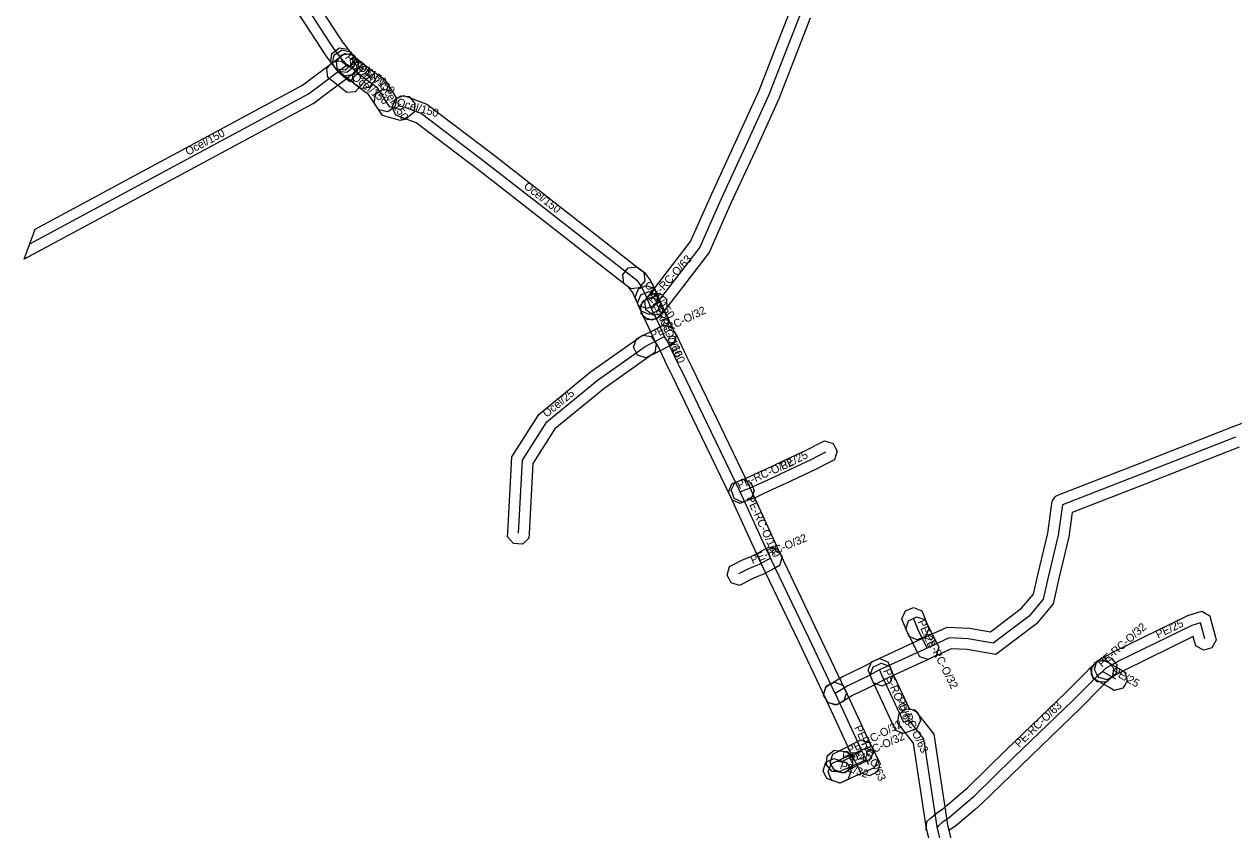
# Model space of a CAD drawing. Extents: x -783553 to -783321, y -1065190 to -1064961.
# Drawn here: x -783552.6 to -783439.3, y -1065147.9 to -1065072.4 of the extents above; entities that cross this region are included whole.
import ezdxf

# ---------------------------------------------------------------- set-up
doc = ezdxf.new("R2010")
doc.units = 0
for name, color, linetype in [('1', 7, 'Continuous'), ('28', 7, 'Continuous'), ('30', 7, 'Continuous'), ('Plyn', 7, 'Continuous')]:
    doc.layers.add(name, color=color, linetype=linetype)

msp = doc.modelspace()

# ---------------------------------------------------------------- linework, layer by layer
at = {"layer": '1'}
for points in [[(-783527.9, -1065066.2), (-783522.74, -1065074.15), (-783522.73, -1065074.15), (-783522.07, -1065075.01), (-783521.81, -1065075.34), (-783521.92, -1065076.16), (-783522.24, -1065076.42), (-783522.57, -1065076.67), (-783523.39, -1065076.57), (-783523.65, -1065076.24), (-783524.38, -1065075.3), (-783524.42, -1065075.24), (-783529.69, -1065067.11)], [(-783479, -1065071.78), (-783480.4, -1065075.41), (-783481.93, -1065079.36), (-783484.16, -1065084.26), (-783486.42, -1065089.15), (-783488.45, -1065093.77), (-783492.65, -1065099.2), (-783492.9, -1065099.53), (-783493.72, -1065099.64), (-783494.05, -1065099.38), (-783494.38, -1065099.13), (-783494.48, -1065098.31), (-783494.23, -1065097.98), (-783490.19, -1065092.74), (-783488.24, -1065088.33), (-783485.98, -1065083.42), (-783483.77, -1065078.58), (-783482.26, -1065074.69), (-783480.88, -1065071.1)], [(-783438.79, -1065112.01), (-783447.61, -1065115.48), (-783454.44, -1065118.14), (-783454.76, -1065120.43), (-783455.71, -1065124.44), (-783456.23, -1065126.71), (-783457.79, -1065128.58), (-783461.59, -1065131.45), (-783464.29, -1065130.98), (-783465.77, -1065130.91), (-783467.6, -1065131.75), (-783472.04, -1065133.8), (-783473, -1065134.31), (-783475.03, -1065135.3), (-783476.15, -1065135.97), (-783476.5, -1065136.18), (-783477.3, -1065135.98), (-783477.52, -1065135.62), (-783477.73, -1065135.27), (-783477.53, -1065134.47), (-783477.17, -1065134.25), (-783475.99, -1065133.54), (-783473.92, -1065132.53), (-783472.94, -1065132), (-783468.44, -1065129.93), (-783466.17, -1065128.89), (-783464.07, -1065128.98), (-783462.1, -1065129.33), (-783459.18, -1065127.12), (-783458.07, -1065125.79), (-783457.65, -1065123.98), (-783456.72, -1065120.07), (-783456.34, -1065117.28), (-783456.3, -1065117.01), (-783455.97, -1065116.59), (-783455.71, -1065116.49), (-783448.33, -1065113.62), (-783439.51, -1065110.15), (-783431.95, -1065107.28)], [(-783468.13, -1065147.92), (-783468.06, -1065147.1), (-783467.74, -1065146.83), (-783467.63, -1065146.74), (-783467.15, -1065146.33), (-783466.56, -1065145.92), (-783465.68, -1065145.17), (-783464.84, -1065144.45), (-783464.26, -1065143.95), (-783460.63, -1065140.4), (-783455.07, -1065135.05), (-783453.09, -1065133.06), (-783452.81, -1065132.76), (-783452.56, -1065132.53), (-783452.26, -1065132.27), (-783451.95, -1065132), (-783451.12, -1065132.06), (-783450.85, -1065132.38), (-783450.58, -1065132.69), (-783450.65, -1065133.52), (-783450.96, -1065133.79), (-783451.22, -1065134.01), (-783451.4, -1065134.18), (-783451.67, -1065134.46), (-783453.67, -1065136.47), (-783459.23, -1065141.84), (-783462.91, -1065145.43), (-783463.54, -1065145.97), (-783464.38, -1065146.69), (-783465.34, -1065147.5), (-783465.93, -1065147.91)], [(-783467.67, -1065149.47), (-783468.08, -1065147.79), (-783469.3, -1065139.75), (-783470.52, -1065138.21), (-783470.77, -1065137.88), (-783470.67, -1065137.06), (-783470.35, -1065136.8), (-783470.02, -1065136.55), (-783469.2, -1065136.65), (-783468.95, -1065136.97), (-783467.4, -1065138.93), (-783466.12, -1065147.41), (-783465.71, -1065149.09)]]:
    msp.add_lwpolyline(points, dxfattribs=at)
for points in [[(-783523.22, -1065076.78), (-783523.48, -1065076.46), (-783523.65, -1065076.24), (-783523.9, -1065075.92), (-783523.8, -1065075.09), (-783523.47, -1065074.84), (-783523.14, -1065074.58), (-783522.32, -1065074.69), (-783522.07, -1065075.01), (-783521.9, -1065075.23), (-783521.65, -1065075.55), (-783521.75, -1065076.37), (-783522.08, -1065076.63), (-783522.4, -1065076.88)], [(-783522.07, -1065074.95), (-783521.86, -1065075.28), (-783521.76, -1065075.35), (-783521.43, -1065075.59), (-783521.29, -1065076.41), (-783521.53, -1065076.74), (-783521.77, -1065077.08), (-783522.58, -1065077.22), (-783522.92, -1065076.98), (-783523.34, -1065076.68), (-783523.53, -1065076.38), (-783523.76, -1065076.03), (-783523.58, -1065075.22), (-783523.23, -1065075), (-783522.88, -1065074.77)], [(-783525.58, -1065079.82), (-783552.64, -1065094.4), (-783551.62, -1065091.57), (-783526.55, -1065078.07), (-783525.27, -1065077.11), (-783523.83, -1065076.03), (-783522.94, -1065075.36), (-783522.61, -1065075.11), (-783521.79, -1065075.23), (-783521.54, -1065075.56), (-783521.3, -1065075.89), (-783521.41, -1065076.71), (-783521.74, -1065076.96), (-783522.63, -1065077.63), (-783524.07, -1065078.71), (-783525.48, -1065079.77), (-783525.55, -1065079.81), (-783525.57, -1065079.81)], [(-783522.61, -1065076.05), (-783522.22, -1065076.36), (-783522.1, -1065076.24), (-783521.82, -1065075.94), (-783520.99, -1065075.91), (-783520.69, -1065076.2), (-783520.39, -1065076.48), (-783520.36, -1065077.31), (-783520.65, -1065077.61), (-783521.01, -1065077.99), (-783521.35, -1065078.39), (-783521.62, -1065078.69), (-783522.42, -1065078.76), (-783522.73, -1065078.51), (-783523.86, -1065077.61), (-783524.18, -1065077.36), (-783524.27, -1065076.53), (-783524.02, -1065076.21), (-783523.76, -1065075.89), (-783522.94, -1065075.79)], [(-783521.13, -1065078.4), (-783521.45, -1065078.14), (-783521.78, -1065077.88), (-783522, -1065077.71), (-783522.96, -1065076.95), (-783523.29, -1065076.69), (-783523.38, -1065075.87), (-783523.13, -1065075.54), (-783522.87, -1065075.22), (-783522.05, -1065075.12), (-783521.72, -1065075.38), (-783520.76, -1065076.14), (-783520.54, -1065076.31), (-783520.21, -1065076.57), (-783519.89, -1065076.82), (-783519.79, -1065077.65), (-783520.05, -1065077.97), (-783520.31, -1065078.3)], [(-783520.57, -1065076.3), (-783520.24, -1065076.55), (-783518.89, -1065077.54), (-783518.45, -1065078.21), (-783518.37, -1065078.34), (-783518.36, -1065078.35), (-783517.96, -1065078.96), (-783517.74, -1065079.31), (-783517.91, -1065080.12), (-783518.25, -1065080.35), (-783518.6, -1065080.57), (-783519.41, -1065080.4), (-783519.64, -1065080.06), (-783520.03, -1065079.45), (-783520.04, -1065079.44), (-783520.13, -1065079.31), (-783520.37, -1065078.94), (-783521.43, -1065078.16), (-783521.76, -1065077.91), (-783521.89, -1065077.09), (-783521.64, -1065076.76), (-783521.39, -1065076.43)], [(-783517.64, -1065079.25), (-783517.61, -1065079.26), (-783517.39, -1065079.08), (-783516.57, -1065079.15), (-783516.3, -1065079.47), (-783516.04, -1065079.79), (-783516.11, -1065080.61), (-783516.43, -1065080.88), (-783516.56, -1065080.99), (-783516.73, -1065081.13), (-783516.92, -1065081.29), (-783517.4, -1065081.39), (-783517.64, -1065081.32), (-783518.18, -1065081.17), (-783519.07, -1065080.92), (-783519.64, -1065080.06), (-783519.86, -1065079.71), (-783519.69, -1065078.9), (-783519.35, -1065078.67), (-783519, -1065078.45), (-783518.19, -1065078.62), (-783517.96, -1065078.96), (-783517.81, -1065079.2)], [(-783517.11, -1065079.03), (-783516.72, -1065079.17), (-783514.92, -1065079.84), (-783508.76, -1065084.52), (-783502.88, -1065089.1), (-783498.15, -1065092.81), (-783494.91, -1065095.34), (-783494.58, -1065095.59), (-783494.48, -1065096.42), (-783494.73, -1065096.74), (-783494.98, -1065097.07), (-783495.81, -1065097.17), (-783496.13, -1065096.92), (-783499.39, -1065094.39), (-783504.12, -1065090.68), (-783509.98, -1065086.1), (-783515.9, -1065081.61), (-783517.42, -1065081.05), (-783517.81, -1065080.9), (-783518.15, -1065080.15), (-783518.01, -1065079.76), (-783517.86, -1065079.37)], [(-783495.23, -1065095.09), (-783494.9, -1065095.34), (-783494.51, -1065095.65), (-783493.93, -1065096.45), (-783493.42, -1065097.5), (-783493.24, -1065097.88), (-783493.51, -1065098.66), (-783493.88, -1065098.84), (-783494.26, -1065099.02), (-783495.04, -1065098.75), (-783495.22, -1065098.38), (-783495.65, -1065097.49), (-783495.97, -1065097.05), (-783496.14, -1065096.92), (-783496.46, -1065096.66), (-783496.56, -1065095.84), (-783496.31, -1065095.51), (-783496.05, -1065095.19)], [(-783494.84, -1065099.27), (-783495, -1065098.89), (-783495.24, -1065098.33), (-783495.4, -1065097.95), (-783495.09, -1065097.18), (-783494.71, -1065097.02), (-783494.33, -1065096.86), (-783493.56, -1065097.17), (-783493.4, -1065097.55), (-783493.16, -1065098.11), (-783493, -1065098.49), (-783493.31, -1065099.26), (-783493.69, -1065099.42), (-783494.07, -1065099.58)], [(-783494.61, -1065099.81), (-783494.77, -1065099.43), (-783495, -1065098.89), (-783495.16, -1065098.51), (-783494.85, -1065097.74), (-783494.47, -1065097.58), (-783494.09, -1065097.42), (-783493.32, -1065097.73), (-783493.16, -1065098.11), (-783492.93, -1065098.65), (-783492.77, -1065099.03), (-783493.08, -1065099.8), (-783493.46, -1065099.96), (-783493.84, -1065100.12)], [(-783477.39, -1065135.91), (-783477.56, -1065135.54), (-783480.03, -1065130.33), (-783483.6, -1065122.85), (-783486.46, -1065116.64), (-783489.57, -1065110.16), (-783491.9, -1065105.36), (-783492.09, -1065104.98), (-783492.39, -1065104.39), (-783492.62, -1065103.89), (-783493.08, -1065102.89), (-783493.18, -1065102.67), (-783493.52, -1065102.1), (-783493.77, -1065101.56), (-783494.09, -1065100.88), (-783494.61, -1065099.75), (-783494.74, -1065099.49), (-783494.93, -1065099.12), (-783494.67, -1065098.33), (-783494.3, -1065098.15), (-783493.93, -1065097.96), (-783493.14, -1065098.22), (-783492.96, -1065098.59), (-783492.81, -1065098.89), (-783492.27, -1065100.04), (-783491.96, -1065100.72), (-783491.74, -1065101.16), (-783491.4, -1065101.75), (-783491.26, -1065102.05), (-783490.8, -1065103.05), (-783490.59, -1065103.52), (-783490.31, -1065104.06), (-783490.1, -1065104.46), (-783487.77, -1065109.3), (-783484.66, -1065115.78), (-783481.8, -1065122.01), (-783478.23, -1065129.47), (-783475.76, -1065134.68), (-783475.58, -1065135.06), (-783475.86, -1065135.84), (-783476.23, -1065136.01), (-783476.61, -1065136.19)], [(-783494.87, -1065098.67), (-783494.59, -1065098.37), (-783494.18, -1065097.92), (-783493.9, -1065097.61), (-783493.07, -1065097.57), (-783492.77, -1065097.85), (-783492.46, -1065098.13), (-783492.42, -1065098.96), (-783492.7, -1065099.26), (-783493.11, -1065099.71), (-783493.39, -1065100.02), (-783494.22, -1065100.06), (-783494.52, -1065099.78), (-783494.83, -1065099.5)], [(-783495.28, -1065101.85), (-783494.91, -1065101.67), (-783494.42, -1065101.42), (-783493.96, -1065101.2), (-783493.31, -1065100.85), (-783493.08, -1065100.74), (-783492.71, -1065100.55), (-783491.92, -1065100.81), (-783491.74, -1065101.18), (-783491.55, -1065101.55), (-783491.81, -1065102.34), (-783492.18, -1065102.52), (-783492.39, -1065102.63), (-783493.06, -1065102.98), (-783493.54, -1065103.22), (-783494.01, -1065103.45), (-783494.38, -1065103.64), (-783495.17, -1065103.38), (-783495.35, -1065103.01), (-783495.54, -1065102.64)], [(-783507.34, -1065120.43), (-783507.32, -1065120.02), (-783506.95, -1065112.91), (-783504.43, -1065108.96), (-783499.56, -1065104.95), (-783495.04, -1065101.75), (-783494.7, -1065101.51), (-783493.88, -1065101.64), (-783493.65, -1065101.98), (-783493.41, -1065102.32), (-783493.54, -1065103.14), (-783493.88, -1065103.38), (-783498.34, -1065106.54), (-783502.92, -1065110.3), (-783504.98, -1065113.54), (-783505.33, -1065120.12), (-783505.35, -1065120.54), (-783505.96, -1065121.09), (-783506.38, -1065121.07), (-783506.79, -1065121.05)], [(-783476.72, -1065113.19), (-783477.09, -1065113.38), (-783478.48, -1065114.1), (-783481.35, -1065115.45), (-783481.48, -1065115.51), (-783483.27, -1065116.32), (-783483.34, -1065116.36), (-783484.22, -1065116.78), (-783484.98, -1065117.04), (-783485.37, -1065117.18), (-783486.11, -1065116.82), (-783486.25, -1065116.43), (-783486.39, -1065116.04), (-783486.03, -1065115.29), (-783485.64, -1065115.16), (-783484.98, -1065114.92), (-783484.31, -1065114.61), (-783484.22, -1065114.55), (-783482.34, -1065113.7), (-783482.23, -1065113.65), (-783479.36, -1065112.3), (-783478.01, -1065111.6), (-783477.64, -1065111.41), (-783476.85, -1065111.66), (-783476.66, -1065112.03), (-783476.47, -1065112.4)], [(-783486.34, -1065115.46), (-783485.96, -1065115.29), (-783485.71, -1065115.19), (-783485.33, -1065115.02), (-783484.56, -1065115.32), (-783484.4, -1065115.7), (-783484.23, -1065116.08), (-783484.53, -1065116.85), (-783484.91, -1065117.02), (-783485.16, -1065117.12), (-783485.54, -1065117.29), (-783486.31, -1065116.99), (-783486.47, -1065116.61), (-783486.64, -1065116.23)], [(-783481.86, -1065123.11), (-783482.23, -1065123.31), (-783483.35, -1065123.91), (-783483.84, -1065124.12), (-783484.48, -1065124.39), (-783485.23, -1065124.78), (-783485.6, -1065124.98), (-783486.39, -1065124.74), (-783486.58, -1065124.37), (-783486.78, -1065124), (-783486.54, -1065123.21), (-783486.17, -1065123.02), (-783485.34, -1065122.57), (-783484.61, -1065122.28), (-783484.21, -1065122.11), (-783483.17, -1065121.55), (-783482.81, -1065121.35), (-783482.02, -1065121.59), (-783481.82, -1065121.96), (-783481.62, -1065122.32)], [(-783468.54, -1065127.36), (-783468.38, -1065127.74), (-783468.02, -1065128.62), (-783467.87, -1065129.01), (-783468.19, -1065129.77), (-783468.57, -1065129.93), (-783468.96, -1065130.08), (-783469.72, -1065129.76), (-783469.88, -1065129.38), (-783470.24, -1065128.5), (-783470.39, -1065128.11), (-783470.07, -1065127.35), (-783469.69, -1065127.19), (-783469.3, -1065127.03)], [(-783468.72, -1065131.66), (-783468.91, -1065131.29), (-783469.84, -1065129.45), (-783470.03, -1065129.08), (-783469.77, -1065128.29), (-783469.4, -1065128.11), (-783469.03, -1065127.92), (-783468.24, -1065128.18), (-783468.06, -1065128.55), (-783467.13, -1065130.39), (-783466.94, -1065130.76), (-783467.2, -1065131.54), (-783467.57, -1065131.73), (-783467.94, -1065131.92)], [(-783442.97, -1065130.23), (-783443.1, -1065129.77), (-783449.64, -1065132.97), (-783450.79, -1065133.61), (-783451.15, -1065133.81), (-783451.95, -1065133.59), (-783452.15, -1065133.23), (-783452.35, -1065132.87), (-783452.13, -1065132.07), (-783451.77, -1065131.87), (-783450.56, -1065131.19), (-783443.61, -1065127.8), (-783442.7, -1065127.52), (-783442.29, -1065127.4), (-783441.92, -1065127.61), (-783441.55, -1065127.81), (-783441.44, -1065128.22), (-783441.04, -1065129.71), (-783440.94, -1065130.11), (-783441.35, -1065130.83), (-783441.75, -1065130.94), (-783442.15, -1065131.05), (-783442.87, -1065130.63)], [(-783471.73, -1065132.13), (-783471.57, -1065132.51), (-783471.38, -1065132.96), (-783471.22, -1065133.34), (-783471.53, -1065134.11), (-783471.91, -1065134.27), (-783472.29, -1065134.43), (-783473.06, -1065134.12), (-783473.22, -1065133.74), (-783473.41, -1065133.29), (-783473.57, -1065132.91), (-783473.26, -1065132.14), (-783472.88, -1065131.98), (-783472.5, -1065131.82)], [(-783471.39, -1065132.93), (-783469.72, -1065136.52), (-783469.69, -1065136.51), (-783468.94, -1065136.85), (-783468.79, -1065137.24), (-783468.65, -1065137.63), (-783468.99, -1065138.38), (-783469.38, -1065138.53), (-783469.89, -1065138.72), (-783470.26, -1065138.85), (-783470.98, -1065138.56), (-783471.15, -1065138.2), (-783473.21, -1065133.77), (-783473.38, -1065133.4), (-783473.1, -1065132.62), (-783472.72, -1065132.44), (-783472.35, -1065132.27), (-783471.57, -1065132.55)], [(-783450.5, -1065134.83), (-783450.86, -1065134.62), (-783452.11, -1065133.89), (-783452.47, -1065133.69), (-783452.68, -1065132.89), (-783452.47, -1065132.53), (-783452.27, -1065132.17), (-783451.46, -1065131.96), (-783451.11, -1065132.17), (-783449.85, -1065132.9), (-783449.5, -1065133.1), (-783449.29, -1065133.9), (-783449.49, -1065134.26), (-783449.7, -1065134.62)], [(-783452.58, -1065132.55), (-783452.27, -1065132.28), (-783451.94, -1065131.99), (-783451.63, -1065131.72), (-783450.8, -1065131.77), (-783450.53, -1065132.08), (-783450.26, -1065132.39), (-783450.31, -1065133.22), (-783450.62, -1065133.49), (-783450.95, -1065133.78), (-783451.26, -1065134.05), (-783452.09, -1065134), (-783452.36, -1065133.69), (-783452.63, -1065133.38)], [(-783475.93, -1065134.31), (-783475.75, -1065134.69), (-783473.25, -1065140.08), (-783472.85, -1065140.86), (-783472.63, -1065141.3), (-783472.44, -1065141.67), (-783472.7, -1065142.46), (-783473.07, -1065142.64), (-783473.44, -1065142.83), (-783474.23, -1065142.57), (-783474.41, -1065142.2), (-783474.63, -1065141.76), (-783475.05, -1065140.96), (-783477.57, -1065135.53), (-783477.74, -1065135.16), (-783477.46, -1065134.38), (-783477.08, -1065134.2), (-783476.71, -1065134.03)], [(-783476.75, -1065140.43), (-783476.34, -1065140.47), (-783475.94, -1065140.5), (-783475.53, -1065140.54), (-783475, -1065141.18), (-783475.03, -1065141.59), (-783475.07, -1065142), (-783475.71, -1065142.53), (-783476.12, -1065142.5), (-783476.52, -1065142.46), (-783476.93, -1065142.42), (-783477.46, -1065141.79), (-783477.43, -1065141.37), (-783477.39, -1065140.96)], [(-783477.03, -1065141.69), (-783476.65, -1065141.52), (-783475.6, -1065141.05), (-783474.15, -1065140.4), (-783473.77, -1065140.23), (-783473, -1065140.52), (-783472.83, -1065140.9), (-783472.66, -1065141.28), (-783472.95, -1065142.05), (-783473.33, -1065142.22), (-783474.78, -1065142.87), (-783475.83, -1065143.34), (-783476.21, -1065143.51), (-783476.98, -1065143.22), (-783477.15, -1065142.84), (-783477.32, -1065142.46)], [(-783473.32, -1065141.22), (-783473.69, -1065141.41), (-783475.11, -1065142.15), (-783475.57, -1065142.39), (-783475.93, -1065142.58), (-783476.72, -1065142.33), (-783476.92, -1065141.96), (-783477.11, -1065141.6), (-783476.86, -1065140.8), (-783476.49, -1065140.61), (-783476.03, -1065140.37), (-783474.61, -1065139.63), (-783474.24, -1065139.44), (-783473.45, -1065139.69), (-783473.26, -1065140.06), (-783473.07, -1065140.43)], [(-783476.76, -1065141.19), (-783476.37, -1065141.33), (-783475.91, -1065141.49), (-783475.52, -1065141.62), (-783475.16, -1065142.36), (-783475.3, -1065142.76), (-783475.43, -1065143.15), (-783476.18, -1065143.51), (-783476.57, -1065143.38), (-783477.02, -1065143.22), (-783477.42, -1065143.08), (-783477.78, -1065142.34), (-783477.64, -1065141.95), (-783477.51, -1065141.55)]]:
    msp.add_lwpolyline(points, close=True, dxfattribs=at)
at = {"layer": '28'}
for points in [[(-783523.23, -1065076.83), (-783522.11, -1065077.73), (-783521.75, -1065077.32), (-783521.38, -1065076.93)], [(-783520.83, -1065077.35), (-783521.16, -1065077.1), (-783521.38, -1065076.93), (-783522.34, -1065076.16)], [(-783520.83, -1065077.35), (-783519.63, -1065078.24), (-783519.29, -1065078.76), (-783519.21, -1065078.89), (-783519.2, -1065078.9), (-783518.8, -1065079.51)], [(-783506.32, -1065120.07), (-783505.96, -1065113.22), (-783503.68, -1065109.63), (-783498.95, -1065105.75), (-783494.46, -1065102.56)], [(-783476.43, -1065141.46), (-783476.03, -1065141.5)], [(-783476.7, -1065142.27), (-783476.24, -1065142.43)]]:
    msp.add_lwpolyline(points, dxfattribs=at)
at = {"layer": 'Plyn'}
for points in [[(-783522.86, -1065075.63), (-783523.56, -1065074.72), (-783523.58, -1065074.7), (-783528.87, -1065066.54), (-783529.24, -1065066.05), (-783527.88, -1065064.84), (-783525.86, -1065054.75), (-783523.6, -1065043.43), (-783521.02, -1065029.36), (-783518.25, -1065015.31), (-783516.38, -1065005.67), (-783514.27, -1064995.29), (-783512.79, -1064989.4), (-783509.96, -1064976.49)], [(-783479.94, -1065071.44), (-783481.33, -1065075.05), (-783482.85, -1065078.97), (-783485.07, -1065083.84), (-783487.33, -1065088.74), (-783489.32, -1065093.25), (-783493.44, -1065098.59)], [(-783522.69, -1065075.84), (-783522.86, -1065075.63)], [(-783522.69, -1065075.84), (-783522.6, -1065075.98), (-783522.34, -1065076.16)], [(-783522.34, -1065076.16), (-783523.23, -1065076.83), (-783524.67, -1065077.91), (-783526.01, -1065078.92), (-783526.03, -1065078.93), (-783552.13, -1065092.98)], [(-783518.8, -1065079.51), (-783518.44, -1065080.06), (-783517.91, -1065080.21), (-783517.37, -1065080.36), (-783517.2, -1065080.22), (-783517.07, -1065080.11)], [(-783517.07, -1065080.11), (-783515.41, -1065080.73), (-783509.37, -1065085.31), (-783503.5, -1065089.89), (-783498.77, -1065093.6), (-783495.52, -1065096.13)], [(-783495.52, -1065096.13), (-783495.24, -1065096.35), (-783494.79, -1065096.97), (-783494.32, -1065097.94)], [(-783494.08, -1065098.5), (-783494.32, -1065097.94)], [(-783493.85, -1065099.04), (-783494.08, -1065098.5)], [(-783493.85, -1065099.04), (-783493.44, -1065098.59)], [(-783476.66, -1065135.11), (-783479.13, -1065129.9), (-783482.7, -1065122.43), (-783485.56, -1065116.21), (-783488.67, -1065109.73), (-783491, -1065104.91), (-783491.2, -1065104.52), (-783491.49, -1065103.95), (-783491.71, -1065103.47), (-783492.17, -1065102.47), (-783492.29, -1065102.21), (-783492.63, -1065101.63), (-783492.86, -1065101.14), (-783493.18, -1065100.46), (-783493.71, -1065099.32), (-783493.85, -1065099.04)], [(-783494.46, -1065102.56), (-783493.98, -1065102.32), (-783493.51, -1065102.09), (-783492.85, -1065101.74), (-783492.63, -1065101.63)], [(-783439.15, -1065111.08), (-783447.97, -1065114.55), (-783455.35, -1065117.42), (-783455.74, -1065120.25), (-783456.68, -1065124.21), (-783457.15, -1065126.25), (-783458.48, -1065127.85), (-783461.85, -1065130.39), (-783464.18, -1065129.98), (-783465.97, -1065129.9), (-783468.02, -1065130.84), (-783472.49, -1065132.9), (-783473.46, -1065133.42), (-783475.51, -1065134.42), (-783476.66, -1065135.11)], [(-783477.55, -1065112.49), (-783478.92, -1065113.2), (-783481.79, -1065114.55), (-783481.91, -1065114.61), (-783483.75, -1065115.44), (-783483.83, -1065115.49), (-783484.6, -1065115.85), (-783485.31, -1065116.1)], [(-783485.56, -1065116.21), (-783485.31, -1065116.1)], [(-783482.7, -1065122.43), (-783483.78, -1065123.01), (-783484.23, -1065123.2), (-783484.91, -1065123.48), (-783485.7, -1065123.9)], [(-783469.31, -1065128.12), (-783468.95, -1065129)], [(-783468.02, -1065130.84), (-783468.95, -1065129)], [(-783442.01, -1065129.97), (-783442.41, -1065128.48), (-783443.24, -1065128.73), (-783450.1, -1065132.08), (-783451.28, -1065132.74)], [(-783472.49, -1065132.9), (-783472.3, -1065133.35)], [(-783472.3, -1065133.35), (-783470.24, -1065137.78), (-783469.73, -1065137.59)], [(-783467.1, -1065147.6), (-783466.98, -1065147.5), (-783466.54, -1065147.12), (-783465.95, -1065146.71), (-783465.03, -1065145.93), (-783464.19, -1065145.21), (-783463.58, -1065144.69), (-783459.93, -1065141.12), (-783454.37, -1065135.76), (-783452.38, -1065133.76), (-783452.1, -1065133.47), (-783451.89, -1065133.27), (-783451.61, -1065133.03)], [(-783451.61, -1065133.03), (-783451.28, -1065132.74)], [(-783450.36, -1065133.76), (-783451.61, -1065133.03)], [(-783476.66, -1065135.11), (-783474.15, -1065140.52), (-783473.74, -1065141.31), (-783473.52, -1065141.75)], [(-783467.9, -1065189.76), (-783467.24, -1065185.39), (-783467.1, -1065184.37), (-783467.14, -1065165.1), (-783467.11, -1065164.71), (-783465.73, -1065164.61), (-783465.73, -1065164.07), (-783466.57, -1065153.34), (-783466.67, -1065149.6), (-783466.67, -1065149.43), (-783466.69, -1065149.28), (-783467.1, -1065147.6), (-783468.35, -1065139.34), (-783469.73, -1065137.59)], [(-783474.15, -1065140.52), (-783475.57, -1065141.26), (-783476.03, -1065141.5)], [(-783476.24, -1065142.43), (-783475.19, -1065141.96), (-783473.74, -1065141.31)]]:
    msp.add_lwpolyline(points, dxfattribs=at)

# ---------------------------------------------------------------- texts
at = {"layer": '30'}
for s, rotation, p in [('PE/160', 307.9308, (-783522.6, -1065075.49)), ('Ocel/150', 324.5468, (-783522.3, -1065075.85)), ('Ocel/150', 321.4831, (-783522.01, -1065077.45)), ('Ocel/150', 321.7329, (-783521.43, -1065076.53)), ('Ocel/150', 303.1785, (-783519.4, -1065078.09)), ('Ocel/150', 344.1975, (-783517.79, -1065079.99)), ('Ocel/150', 28.3066, (-783537.29, -1065084.69)), ('Ocel/150', 322.0373, (-783505.89, -1065087.67)), ('PE-RC-O/63', 47.663, (-783493.81, -1065098.58)), ('Ocel/150', 305.9724, (-783494.57, -1065096.79)), ('PE-RC-O/160', 293.1986, (-783494.02, -1065097.97)), ('PE-RC-O/160', 293.0704, (-783493.78, -1065098.52)), ('PE-RC-O/32', 26.0754, (-783493.74, -1065101.9)), ('Ocel/25', 39.3903, (-783503.68, -1065109.27)), ('PE-RC-O/32', 23.7495, (-783485.64, -1065115.96)), ('PE/25', 25.1675, (-783481.6, -1065114.16)), ('PE-RC-O/160', 294.6933, (-783485, -1065116.79)), ('PE-RC-O/32', 22.8906, (-783484.39, -1065122.98)), ('PE/25', 292.2035, (-783468.93, -1065128.36)), ('PE-RC-O/32', 41.3086, (-783451.65, -1065132.69)), ('PE/25', 26.028, (-783446.39, -1065129.97)), ('PE-RC-O/32', 296.8136, (-783468.29, -1065129.72)), ('PE/25', 329.7891, (-783450.78, -1065133.19)), ('PE-RC-O/63', 292.8906, (-783472.18, -1065132.97)), ('PE-RC-O/63', 294.939, (-783470.93, -1065135.66)), ('PE-RC-O/63', 43.9507, (-783459.4, -1065140.22)), ('PE-RC-O/32', 27.5252, (-783475.29, -1065140.81)), ('PE-RC-O/63', 294.8892, (-783474.89, -1065138.29)), ('PE-RC-O/32', 24.1455, (-783475.19, -1065141.67)), ('PE/40', 354.8572, (-783476.03, -1065141.28)), ('PE/32', 340.9667, (-783476.27, -1065142.15))]:
    msp.add_text(s, height=0.75, rotation=rotation, dxfattribs=at).set_placement(p)

doc.saveas('drawing.dxf')
